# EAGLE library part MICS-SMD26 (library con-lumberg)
CONNECTOR
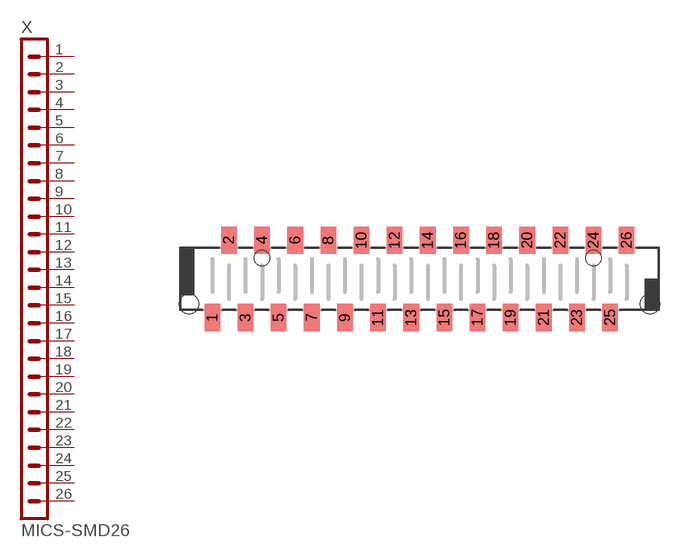
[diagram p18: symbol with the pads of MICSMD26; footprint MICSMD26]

Designator prefix X

## MICS-SMD26 (OC_FARNELL: unknown; OC_NEWARK: unknown)  [MICSMD26]
1  1  pas
2  2  pas
3  3  pas
4  4  pas
5  5  pas
6  6  pas
7  7  pas
8  8  pas
9  9  pas
10  10  pas
11  11  pas
12  12  pas
13  13  pas
14  14  pas
15  15  pas
16  16  pas
17  17  pas
18  18  pas
19  19  pas
20  20  pas
21  21  pas
22  22  pas
23  23  pas
24  24  pas
25  25  pas
26  26  pas

## Footprint MICSMD26 (pad centres in mm)
CONNECTOR
smd 1.2 x 2.1: 1 -15.875,-2.959; 2 -14.605,2.959; 3 -13.335,-2.959; 4 -12.065,2.959; 5 -10.795,-2.959; 6 -9.525,2.959; 7 -8.255,-2.959; 8 -6.985,2.959; 9 -5.715,-2.959; 10 -4.445,2.959; 11 -3.175,-2.959; 12 -1.905,2.959; 13 -0.635,-2.959; 14 0.635,2.959; 15 1.905,-2.959; 16 3.175,2.959; 17 4.445,-2.959; 18 5.715,2.959; 19 6.985,-2.959; 20 8.255,2.959; 21 9.525,-2.959; 22 10.795,2.959; 23 12.065,-2.959; 24 13.335,2.959; 25 14.605,-2.959; 26 15.875,2.959
hole 1.5 at 17.675,-1.912
hole 1.5 at -17.675,-1.912
hole 1.2 at -12.065,1.6
hole 1.2 at 13.335,1.6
